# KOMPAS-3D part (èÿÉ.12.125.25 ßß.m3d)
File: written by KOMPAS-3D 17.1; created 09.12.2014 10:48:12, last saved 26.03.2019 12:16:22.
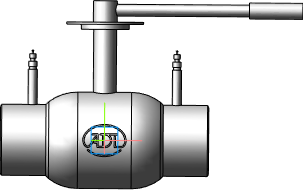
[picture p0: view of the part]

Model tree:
1. Операция без истории:5  (labels: Сталь 20  ГОСТ 1050-88)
